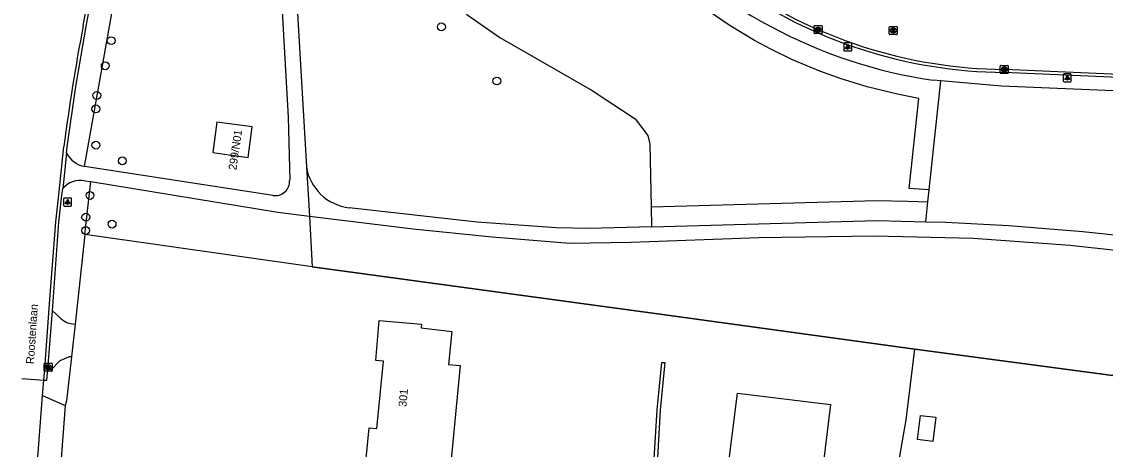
# Model space of a CAD drawing. Extents: x 162157 to 163165, y 378998 to 380775.
# Drawn here: x 162215.9 to 162351.3, y 380360.2 to 380413.6 of the extents above; entities that cross this region are included whole.
import ezdxf

# ---------------------------------------------------------------- set-up
doc = ezdxf.new("R2010")
doc.units = 0
for name, color, linetype in [('IMGEO_Berm_open', 7, 'Continuous'), ('IMGEO_Boom', 7, 'Continuous'), ('IMGEO_Gemengd_bos', 7, 'Continuous'), ('IMGEO_Groenvoorziening', 7, 'Continuous'), ('IMGEO_Haag', 7, 'Continuous'), ('IMGEO_Hek', 7, 'Continuous'), ('IMGEO_Kolk', 7, 'Continuous'), ('IMGEO_Lichtpunt', 7, 'Continuous'), ('IMGEO_Loofbos', 7, 'Continuous'), ('IMGEO_Openbare_ruimte_label', 7, 'Continuous'), ('IMGEO_Pand', 7, 'Continuous'), ('IMGEO_Pand_nummerreeks', 7, 'Continuous'), ('IMGEO_Pand_vergunning_verleend', 7, 'Continuous'), ('IMGEO_Rijbaan_lokaal_gesloten', 7, 'Continuous'), ('IMGEO_Rijbaan_lokaal_open', 7, 'Continuous'), ('IMGEO_Rioolput', 7, 'Continuous'), ('IMGEO_Voetpad_halfverhard', 7, 'Continuous'), ('IMGEO_Voetpad_open', 7, 'Continuous')]:
    doc.layers.add(name, color=color, linetype=linetype)

msp = doc.modelspace()

# ---------------------------------------------------------------- linework, layer by layer
at = {"layer": 'IMGEO_Berm_open'}
for points in [[(162221.52, 380397.19), (162221.61, 380397.97), (162222.69, 380405.52), (162224, 380413.04), (162234.46, 380470.08)], [(162219.76, 380377.51), (162220.59, 380388.58), (162220.96, 380391.95), (162221.05, 380392.78)], [(162218.68, 380368.84), (162219.08, 380368.81), (162219.2, 380370.14)]]:
    msp.add_lwpolyline(points, dxfattribs=at)
at = {"layer": 'IMGEO_Boom'}
for centre in [(162268.37, 380412.98), (162227.1, 380411.26), (162226.37, 380408.12), (162275.3, 380406.22), (162225.31, 380404.41), (162225.2, 380402.73), (162225.2, 380398.19), (162228.5, 380396.24), (162224.47, 380391.91), (162223.95, 380389.2), (162227.22, 380388.33), (162223.92, 380387.53)]:
    msp.add_circle(centre, 0.489, dxfattribs=at)
at = {"layer": 'IMGEO_Gemengd_bos'}
for points in [[(162223.77, 380395.54), (162237.02, 380469.79)], [(162272.58, 380455.26), (162272.5, 380454.79), (162270.97, 380452.4), (162264.79, 380447.49), (162262.15, 380444.96), (162261.21, 380443.7), (162260.84, 380442.91), (162261.06, 380442.15), (162262.3, 380440.07), (162263.71, 380431.53), (162265.17, 380424.18), (162266.96, 380419.94), (162268.47, 380417.76), (162269.99, 380416), (162271.55, 380414.51), (162275.66, 380411.65), (162287.19, 380405.04), (162292.56, 380401.47), (162294.14, 380399.4), (162294.42, 380398.33), (162294.56, 380390.49)], [(162223.82, 380387.03), (162224.55, 380393.64)], [(162294.56, 380390.49), (162294.61, 380387.99)], [(162252.22, 380382.98), (162223.82, 380387.03)]]:
    msp.add_lwpolyline(points, dxfattribs=at)
at = {"layer": 'IMGEO_Groenvoorziening'}
for points in [[(162329.3, 380392.61), (162326.81, 380392.79), (162328.01, 380404.04), (162325.52, 380404.53), (162321.57, 380405.5), (162318.32, 380406.49), (162315.65, 380407.46), (162312.25, 380408.88), (162309.52, 380410.2), (162307.47, 380411.29), (162304.3, 380413.18), (162300.37, 380415.89), (162297.09, 380418.51), (162293.24, 380422.07), (162290.85, 380424.61), (162292.66, 380426.34)], [(162329.3, 380392.61), (162330.76, 380406.23)], [(162329.14, 380391.1), (162329.3, 380392.61)], [(162294.56, 380390.49), (162322.78, 380391.28), (162326.63, 380391.18), (162329.14, 380391.1)], [(162328.88, 380388.63), (162329.14, 380391.1)], [(162223.82, 380387.03), (162222.59, 380375.84)], [(162222.14, 380371.75), (162221.53, 380366.25), (162221.34, 380365.66)]]:
    msp.add_lwpolyline(points, dxfattribs=at)
at = {"layer": 'IMGEO_Haag'}
msp.add_lwpolyline([(162293.89, 380344.29), (162293.49, 380344.32), (162294.02, 380350.65), (162294.88, 380357.67), (162295.31, 380365.11), (162295.89, 380371.05), (162296.29, 380371.02), (162295.71, 380365.08), (162295.28, 380357.64), (162294.42, 380350.61), (162293.89, 380344.29)], dxfattribs=at)
at = {"layer": 'IMGEO_Hek'}
for points in [[(162223.82, 380387.03), (162222.59, 380375.84)], [(162252.22, 380382.98), (162223.82, 380387.03)], [(162295.98, 380377.02), (162252.22, 380382.98)], [(162327.51, 380372.72), (162295.98, 380377.02)], [(162222.59, 380375.84), (162222.14, 380371.75)], [(162323.41, 380344.98), (162324.07, 380348.88), (162324.46, 380352.61), (162326.45, 380363.87), (162327.51, 380372.72)], [(162470.61, 380314.58), (162467.48, 380319.24), (162460.73, 380328.61), (162459.47, 380329.99), (162454.14, 380337.89), (162448.06, 380346.22), (162447.12, 380347.84), (162440.5, 380357.48), (162424.53, 380359.77), (162327.51, 380372.72)]]:
    msp.add_lwpolyline(points, dxfattribs=at)
at = {"layer": 'IMGEO_Kolk'}
for p, q in [((162314.93, 380412.22), (162314.93, 380413.07)), ((162315, 380413.14), (162315.85, 380413.14)), ((162315.85, 380412.14), (162315, 380412.14)), ((162315.41, 380412.92), (162315.44, 380412.92)), ((162315.44, 380412.36), (162315.41, 380412.36)), ((162315.93, 380413.07), (162315.93, 380412.22)), ((162338.19, 380407.23), (162338.19, 380408.08)), ((162338.27, 380408.16), (162339.12, 380408.16)), ((162338.68, 380407.94), (162338.71, 380407.94)), ((162339.19, 380408.08), (162339.19, 380407.23)), ((162339.12, 380407.16), (162338.27, 380407.16)), ((162338.7, 380407.38), (162338.68, 380407.38)), ((162218.74, 380370.02), (162218.74, 380370.87)), ((162218.82, 380370.95), (162219.67, 380370.95)), ((162219.67, 380369.94), (162218.82, 380369.94)), ((162219.23, 380370.72), (162219.25, 380370.72)), ((162219.25, 380370.17), (162219.23, 380370.17)), ((162219.74, 380370.87), (162219.74, 380370.02))]:
    msp.add_line(p, q, dxfattribs=at)
for points in [[(162314.93, 380412.22), (162314.93, 380413.07)], [(162315, 380413.14), (162315.85, 380413.14)], [(162315.85, 380412.14), (162315, 380412.14)], [(162315.25, 380412.84), (162315.37, 380412.84), (162315.37, 380412.69), (162315.5, 380412.84), (162315.66, 380412.84), (162315.52, 380412.69), (162315.67, 380412.44), (162315.52, 380412.44), (162315.43, 380412.61), (162315.37, 380412.54), (162315.37, 380412.44), (162315.25, 380412.44), (162315.25, 380412.84)], [(162315.93, 380413.07), (162315.93, 380412.22)], [(162338.19, 380407.23), (162338.19, 380408.08)], [(162338.27, 380408.16), (162339.12, 380408.16)], [(162338.51, 380407.86), (162338.64, 380407.86), (162338.64, 380407.71), (162338.77, 380407.86), (162338.93, 380407.86), (162338.79, 380407.71), (162338.94, 380407.46), (162338.79, 380407.46), (162338.7, 380407.62), (162338.64, 380407.56), (162338.64, 380407.46), (162338.51, 380407.46), (162338.51, 380407.86)], [(162339.19, 380408.08), (162339.19, 380407.23)], [(162339.12, 380407.16), (162338.27, 380407.16)], [(162218.74, 380370.02), (162218.74, 380370.87)], [(162218.82, 380370.95), (162219.67, 380370.95)], [(162219.67, 380369.94), (162218.82, 380369.94)], [(162219.06, 380370.64), (162219.19, 380370.64), (162219.19, 380370.49), (162219.31, 380370.64), (162219.48, 380370.64), (162219.33, 380370.49), (162219.49, 380370.24), (162219.33, 380370.24), (162219.25, 380370.41), (162219.19, 380370.34), (162219.19, 380370.24), (162219.06, 380370.24), (162219.06, 380370.64)], [(162219.74, 380370.87), (162219.74, 380370.02)]]:
    msp.add_lwpolyline(points, dxfattribs=at)
for centre, start, end in [((162315, 380413.07), 91.552, 178.448), ((162315, 380413.07), 91.552, 178.448), ((162315, 380412.22), 181.552, 268.448), ((162315, 380412.22), 181.552, 268.448), ((162315.85, 380413.07), 1.552, 88.448), ((162315.85, 380413.07), 1.552, 88.448), ((162315.85, 380412.22), 271.552, 358.448), ((162315.85, 380412.22), 271.552, 358.448), ((162338.27, 380408.08), 91.552, 178.448), ((162338.27, 380408.08), 91.552, 178.448), ((162339.12, 380408.08), 1.552, 88.448), ((162339.12, 380408.08), 1.552, 88.448), ((162338.27, 380407.23), 181.552, 268.448), ((162338.27, 380407.23), 181.552, 268.448), ((162339.12, 380407.23), 271.552, 358.448), ((162339.12, 380407.23), 271.552, 358.448), ((162218.82, 380370.87), 91.552, 178.448), ((162218.82, 380370.87), 91.552, 178.448), ((162218.82, 380370.02), 181.552, 268.448), ((162218.82, 380370.02), 181.552, 268.448), ((162219.67, 380370.87), 1.552, 88.448), ((162219.67, 380370.87), 1.552, 88.448), ((162219.67, 380370.02), 271.552, 358.448), ((162219.67, 380370.02), 271.552, 358.448)]:
    msp.add_arc(centre, 0.0765, start, end, dxfattribs=at)
for centre, major_axis, ratio, start_param, end_param in [((162315.41, 380412.64), (-0.387, 0.002), 0.722429, 4.712389, 7.853982), ((162315.44, 380412.64), (-0.39, 0.002), 0.717154, 1.570796, 4.712389), ((162338.68, 380407.66), (-0.387, 0.002), 0.722429, 4.712389, 7.853982), ((162338.7, 380407.66), (-0.39, 0.002), 0.717154, 1.570796, 4.712389), ((162219.23, 380370.44), (-0.387, 0.002), 0.722429, 4.712389, 7.853982), ((162219.25, 380370.44), (-0.39, 0.002), 0.717154, 1.570796, 4.712389)]:
    msp.add_ellipse(centre, major_axis=major_axis, ratio=ratio, start_param=start_param, end_param=end_param, dxfattribs=at)
at = {"layer": 'IMGEO_Lichtpunt'}
for p, q in [((162318.64, 380410.88), (162318.64, 380410.07)), ((162318.64, 380410.88), (162318.64, 380410.07)), ((162319.54, 380410.97), (162318.73, 380410.97)), ((162319.54, 380410.97), (162318.73, 380410.97)), ((162319.63, 380410.07), (162319.63, 380410.88)), ((162319.63, 380410.07), (162319.63, 380410.88)), ((162318.73, 380409.97), (162319.54, 380409.97)), ((162318.73, 380409.97), (162319.54, 380409.97)), ((162346.06, 380407.01), (162346.06, 380406.21)), ((162346.06, 380407.01), (162346.06, 380406.21)), ((162346.96, 380407.11), (162346.16, 380407.11)), ((162346.96, 380407.11), (162346.16, 380407.11)), ((162347.06, 380406.21), (162347.06, 380407.01)), ((162347.06, 380406.21), (162347.06, 380407.01)), ((162346.16, 380406.11), (162346.96, 380406.11)), ((162346.16, 380406.11), (162346.96, 380406.11)), ((162222.07, 380391.59), (162221.26, 380391.59)), ((162222.07, 380391.59), (162221.26, 380391.59)), ((162221.16, 380391.49), (162221.16, 380390.69)), ((162221.16, 380391.49), (162221.16, 380390.69)), ((162221.26, 380390.59), (162222.07, 380390.59)), ((162221.26, 380390.59), (162222.07, 380390.59)), ((162222.16, 380390.69), (162222.16, 380391.49)), ((162222.16, 380390.69), (162222.16, 380391.49))]:
    msp.add_line(p, q, dxfattribs=at)
for points in [[(162319.01, 380410.54), (162319.05, 380410.51), (162318.86, 380410.25), (162318.82, 380410.28), (162319.01, 380410.54)], [(162319.11, 380410.49), (162319.16, 380410.49), (162319.16, 380410.17), (162319.11, 380410.17), (162319.11, 380410.49)], [(162319.22, 380410.51), (162319.26, 380410.54), (162319.45, 380410.28), (162319.41, 380410.25), (162319.22, 380410.51)], [(162346.44, 380406.68), (162346.48, 380406.65), (162346.29, 380406.39), (162346.25, 380406.41), (162346.44, 380406.68)], [(162346.54, 380406.63), (162346.59, 380406.63), (162346.59, 380406.31), (162346.54, 380406.31), (162346.54, 380406.63)], [(162346.65, 380406.65), (162346.69, 380406.68), (162346.87, 380406.41), (162346.84, 380406.39), (162346.65, 380406.65)], [(162221.54, 380391.16), (162221.58, 380391.13), (162221.39, 380390.87), (162221.35, 380390.9), (162221.54, 380391.16)], [(162221.64, 380391.11), (162221.69, 380391.11), (162221.69, 380390.79), (162221.64, 380390.79), (162221.64, 380391.11)], [(162221.75, 380391.13), (162221.79, 380391.16), (162221.98, 380390.89), (162221.94, 380390.87), (162221.75, 380391.13)]]:
    msp.add_lwpolyline(points, dxfattribs=at)
for centre in [(162319.14, 380410.67), (162346.56, 380406.81), (162221.66, 380391.29)]:
    msp.add_circle(centre, 0.0994, dxfattribs=at)
for centre, start, end in [((162318.73, 380410.88), 90, 180), ((162318.73, 380410.88), 90, 180), ((162319.54, 380410.88), 0, 90), ((162319.54, 380410.88), 0, 90), ((162318.73, 380410.07), 180, 270), ((162318.73, 380410.07), 180, 270), ((162319.54, 380410.07), 270, 0), ((162319.54, 380410.07), 270, 360), ((162346.16, 380407.01), 90, 180), ((162346.16, 380407.01), 90, 180), ((162346.96, 380407.01), 0, 90), ((162346.96, 380407.01), 0, 90), ((162346.16, 380406.21), 180, 270), ((162346.16, 380406.21), 180, 270), ((162346.96, 380406.21), 270, 0), ((162346.96, 380406.21), 270, 360), ((162221.26, 380391.49), 90, 180), ((162221.26, 380391.49), 90, 180), ((162222.07, 380391.49), 0, 90), ((162222.07, 380391.49), 0, 90), ((162221.26, 380390.69), 180, 270), ((162221.26, 380390.69), 180, 270), ((162222.07, 380390.69), 270, 0), ((162222.07, 380390.69), 270, 360)]:
    msp.add_arc(centre, 0.0946, start, end, dxfattribs=at)
at = {"layer": 'IMGEO_Loofbos'}
for points in [[(162251.9, 380389.34), (162252.22, 380382.98)], [(162252.22, 380382.98), (162295.98, 380377.02), (162327.51, 380372.72), (162424.53, 380359.77), (162440.5, 380357.48), (162447.12, 380347.84), (162448.06, 380346.22), (162454.14, 380337.89), (162459.47, 380329.99), (162460.73, 380328.61), (162467.48, 380319.24), (162470.61, 380314.58)]]:
    msp.add_lwpolyline(points, dxfattribs=at)
at = {"layer": 'IMGEO_Pand'}
for points in [[(162244.21, 380396.67), (162244.73, 380400.48), (162240.31, 380401.08), (162239.79, 380397.27), (162244.21, 380396.67)], [(162258.63, 380355.6), (162259.33, 380362.87), (162260.31, 380362.78), (162261.15, 380371.22), (162260.17, 380371.27), (162260.6, 380376.29), (162265.87, 380375.83), (162265.83, 380375.36), (162269.65, 380374.91), (162269.25, 380370.79), (162270.73, 380370.65), (162269.17, 380354.58), (162258.63, 380355.6)]]:
    msp.add_lwpolyline(points, dxfattribs=at)
at = {"layer": 'IMGEO_Pand_vergunning_verleend'}
for points in [[(162304, 380356.27), (162305.34, 380367.21), (162316.98, 380365.79), (162315.64, 380354.85), (162304, 380356.27)], [(162327.84, 380361.43), (162328.23, 380364.42), (162330.14, 380364.18), (162329.75, 380361.18), (162327.84, 380361.43)]]:
    msp.add_lwpolyline(points, dxfattribs=at)
at = {"layer": 'IMGEO_Rijbaan_lokaal_gesloten'}
for points in [[(162223.61, 380413.11), (162234.07, 380470.13), (162237.85, 380490.74)], [(162521.14, 380393.2), (162509.49, 380394.72), (162500, 380396.02), (162478.6, 380398.95), (162459.41, 380401.55), (162449.88, 380402.37), (162442.49, 380403.08), (162422.86, 380404.13), (162401.88, 380404.98), (162358.73, 380406.8), (162338.7, 380407.66)], [(162218.68, 380368.84), (162218.8, 380370.18), (162219.38, 380377.84), (162220.2, 380388.61), (162220.56, 380391.99), (162221.21, 380398.02)]]:
    msp.add_lwpolyline(points, dxfattribs=at)
for centre, radius, start, end in [((162339.22, 380466.92), 59.26, 234.584, 269.492), ((162463.68, 380367.21), 244.42, 169.1747, 172.7584)]:
    msp.add_arc(centre, radius, start, end, dxfattribs=at)
at = {"layer": 'IMGEO_Rijbaan_lokaal_open'}
for points in [[(162521.09, 380392.82), (162509.45, 380394.35), (162500, 380395.64), (162478.55, 380398.58), (162459.37, 380401.17), (162449.85, 380401.99), (162442.47, 380402.7), (162422.84, 380403.75), (162401.86, 380404.6), (162358.71, 380406.42), (162338.69, 380407.28)], [(162215.93, 380369.05), (162215.93, 380369.05), (162218.68, 380368.84)], [(162218.54, 380366.91), (162218.68, 380368.84)], [(162217.85, 380358.08), (162218.54, 380366.91)]]:
    msp.add_lwpolyline(points, dxfattribs=at)
msp.add_arc((162339.21, 380466.89), 59.61, 234.5798, 269.4955, dxfattribs=at)
at = {"layer": 'IMGEO_Rioolput'}
for p, q in [((162324.32, 380412.1), (162324.32, 380412.95)), ((162324.39, 380413.03), (162325.24, 380413.03)), ((162325.24, 380412.03), (162324.39, 380412.03)), ((162324.83, 380412.25), (162324.8, 380412.25)), ((162324.81, 380412.81), (162324.83, 380412.81)), ((162325.32, 380412.95), (162325.32, 380412.1))]:
    msp.add_line(p, q, dxfattribs=at)
for points in [[(162324.32, 380412.1), (162324.32, 380412.95)], [(162324.39, 380413.03), (162325.24, 380413.03)], [(162325.24, 380412.03), (162324.39, 380412.03)], [(162324.91, 380412.72), (162324.65, 380412.73), (162324.65, 380412.33)], [(162324.65, 380412.33), (162324.78, 380412.33), (162324.78, 380412.49), (162324.79, 380412.49)], [(162324.83, 380412.65), (162324.78, 380412.65), (162324.78, 380412.56)], [(162324.78, 380412.56), (162324.83, 380412.56)], [(162324.84, 380412.46), (162324.91, 380412.33), (162325.05, 380412.33), (162324.98, 380412.45)], [(162325.32, 380412.95), (162325.32, 380412.1)]]:
    msp.add_lwpolyline(points, dxfattribs=at)
for centre, radius, start, end in [((162324.39, 380412.95), 0.0765, 91.552, 178.448), ((162324.39, 380412.95), 0.0765, 91.552, 178.448), ((162324.39, 380412.1), 0.0765, 181.552, 268.448), ((162324.39, 380412.1), 0.0765, 181.552, 268.448), ((162324.79, 380412.44), 0.0533, 26.0293, 88.6989), ((162324.84, 380412.55), 0.0964, 77.0061, 93.1865), ((162324.81, 380412.75), 0.19, 274.7715, 282.9687), ((162324.85, 380412.61), 0.0378, 276.6634, 79.6772), ((162324.91, 380412.61), 0.109, 350.3612, 89.416), ((162324.9, 380412.61), 0.112, 277.5842, 350.9817), ((162324.89, 380412.4), 0.108, 29.5134, 73.7905), ((162325.24, 380412.95), 0.0765, 1.552, 88.448), ((162325.24, 380412.95), 0.0765, 1.552, 88.448), ((162325.24, 380412.1), 0.0765, 271.552, 358.448), ((162325.24, 380412.1), 0.0765, 271.552, 358.448)]:
    msp.add_arc(centre, radius, start, end, dxfattribs=at)
for centre, major_axis, ratio, start_param, end_param in [((162324.8, 380412.53), (-0.387, 0.002), 0.722429, 4.712389, 7.853982), ((162324.83, 380412.53), (-0.39, 0.002), 0.717154, 1.570796, 4.712389)]:
    msp.add_ellipse(centre, major_axis=major_axis, ratio=ratio, start_param=start_param, end_param=end_param, dxfattribs=at)
at = {"layer": 'IMGEO_Voetpad_halfverhard'}
for points in [[(162253.13, 380493.2), (162253.93, 380491.17), (162252.83, 380484.25), (162248.24, 380458.76), (162246.93, 380442.12), (162249.21, 380401.69), (162249.41, 380393.79)], [(162249.76, 380425.3), (162251.5, 380395.48)], [(162221.52, 380397.19), (162221.05, 380392.78)], [(162247.33, 380391.92), (162223.77, 380395.54)], [(162251.5, 380395.48), (162251.9, 380389.34)], [(162223.79, 380393.76), (162224.55, 380393.64)], [(162224.55, 380393.64), (162247.93, 380389.84), (162251.9, 380389.34)], [(162294.61, 380387.99), (162286.82, 380387.77), (162282.71, 380387.86), (162272.85, 380388.58), (162256.83, 380390.36)], [(162251.9, 380389.34), (162264.82, 380387.74), (162274.72, 380386.73), (162284.42, 380385.96), (162292.09, 380386.08), (162308.03, 380386.67), (162322.49, 380386.86), (162334.81, 380386.58), (162346.93, 380385.68), (162363.18, 380383.92), (162370.05, 380382.82), (162377.36, 380381.45), (162390.62, 380377.99), (162397.84, 380375.75), (162404.34, 380373.96), (162410.16, 380372.59), (162431.24, 380368.18), (162437.86, 380366.02), (162441.68, 380364.52)], [(162294.61, 380387.99), (162322.79, 380388.77), (162328.88, 380388.63)], [(162328.88, 380388.63), (162331.38, 380388.57), (162339.24, 380388.16), (162348.52, 380387.39), (162357.98, 380386.41), (162364.92, 380385.44), (162371.19, 380384.55), (162378.04, 380383.27)]]:
    msp.add_lwpolyline(points, dxfattribs=at)
for centre, radius, start, end in [((162224.4, 380398.74), 3.26, 208.4377, 258.9817), ((162257.59, 380396.5), 6.18, 189.4276, 262.9178), ((162223.29, 380390.84), 2.96, 80.2943, 139.2221), ((162247.62, 380393.68), 1.79, 260.4081, 3.4475)]:
    msp.add_arc(centre, radius, start, end, dxfattribs=at)
at = {"layer": 'IMGEO_Voetpad_open'}
for points in [[(162330.76, 380406.23), (162329.79, 380406.31)], [(162392.23, 380403.34), (162338.34, 380405.57), (162330.76, 380406.23)], [(162219.2, 380370.14), (162219.76, 380377.51)], [(162220.63, 380376.75), (162219.76, 380377.51)], [(162222.59, 380375.84), (162222.14, 380371.75)], [(162220.7, 380371.24), (162219.6, 380370.11), (162219.2, 380370.14)], [(162222.14, 380371.75), (162221.88, 380371.73)], [(162218.54, 380366.91), (162221.34, 380365.66)], [(162221.34, 380365.66), (162220.76, 380357.89)]]:
    msp.add_lwpolyline(points, dxfattribs=at)
for centre, radius, start, end in [((162338.75, 380467.36), 61.7, 221.6689, 261.6444), ((162222.53, 380378.28), 2.44, 218.8515, 271.2943), ((162223.38, 380366.47), 5.46, 105.8864, 119.2703)]:
    msp.add_arc(centre, radius, start, end, dxfattribs=at)

# ---------------------------------------------------------------- texts
at = {"layer": 'IMGEO_Openbare_ruimte_label'}
msp.add_text('Roostenlaan', height=1, rotation=86.1593, dxfattribs=at).set_placement((162217.46, 380370.81))
at = {"layer": 'IMGEO_Pand_nummerreeks'}
for s, rotation, p in [('299/N01', 81.6341, (162242.74, 380395.04)), ('301', 84.6569, (162263.99, 380365.46))]:
    msp.add_text(s, height=1, rotation=rotation, dxfattribs=at).set_placement(p)

doc.saveas('drawing.dxf')
